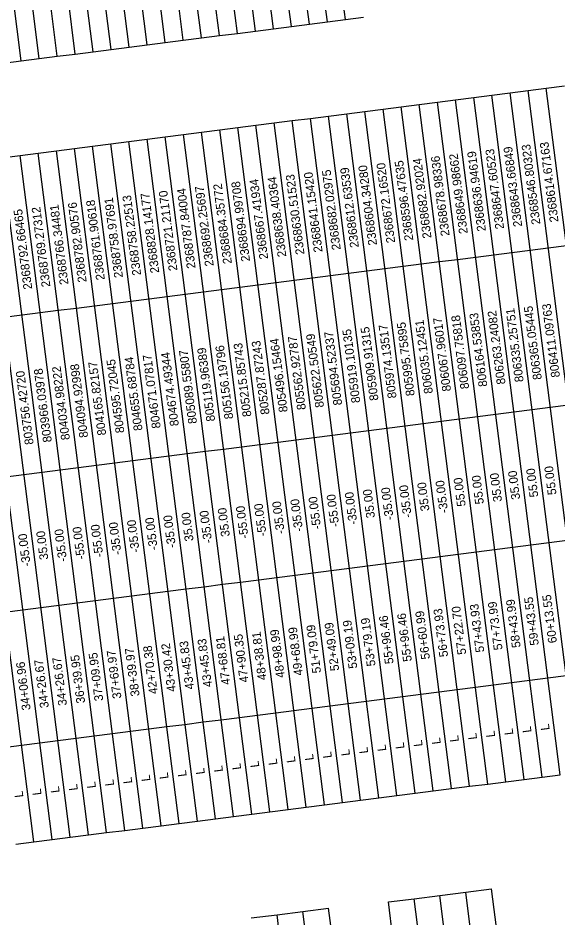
# Model space of a CAD drawing. Extents: x 2364621 to 2374814, y 792603 to 806745.
# Drawn here: x 2368280 to 2369750, y 798784 to 801237 of the extents above; entities that cross this region are included whole.
import ezdxf

# ---------------------------------------------------------------- set-up
doc = ezdxf.new("R2010")
doc.units = 0
doc.layers.add('CTL Sheet Table Cell', color=7, linetype='Continuous')
doc.layers.add('CTL Sheet Text', color=7, linetype='Continuous')

msp = doc.modelspace()

# ---------------------------------------------------------------- linework, layer by layer
at = {"layer": 'CTL Sheet Table Cell'}
for p, q in [((2369025.4, 801214.3), (2368791.2, 803048)), ((2369074.6, 801220.5), (2368840.4, 803054.3)), ((2369123.7, 801226.8), (2368889.5, 803060.6)), ((2369172.8, 801233.1), (2368938.6, 803066.8)), ((2368829, 801189.2), (2368594.8, 803022.9)), ((2368878.1, 801195.4), (2368643.9, 803029.2)), ((2368927.2, 801201.7), (2368693, 803035.5)), ((2368976.3, 801208), (2368742.1, 803041.7)), ((2368632.5, 801164.1), (2368398.3, 802997.8)), ((2368681.6, 801170.4), (2368447.4, 803004.1)), ((2368730.7, 801176.6), (2368496.5, 803010.4)), ((2368779.9, 801182.9), (2368545.7, 803016.6)), ((2368436, 801139), (2368201.8, 802972.7)), ((2368485.1, 801145.3), (2368250.9, 802979)), ((2368534.3, 801151.5), (2368300.1, 802985.3)), ((2368583.4, 801157.8), (2368349.2, 802991.5)), ((2368288.7, 801120.2), (2368054.5, 802953.9)), ((2368337.8, 801126.4), (2368103.6, 802960.2)), ((2368386.9, 801132.7), (2368152.7, 802966.5)), ((2369123.7, 801226.8), (2369172.8, 801233.1)), ((2369172.8, 801233.1), (2369221.9, 801239.4)), ((2368927.2, 801201.7), (2368976.3, 801208)), ((2368976.3, 801208), (2369025.4, 801214.3)), ((2369025.4, 801214.3), (2369074.6, 801220.5)), ((2369074.6, 801220.5), (2369123.7, 801226.8)), ((2368730.7, 801176.6), (2368779.9, 801182.9)), ((2368779.9, 801182.9), (2368829, 801189.2)), ((2368829, 801189.2), (2368878.1, 801195.4)), ((2368878.1, 801195.4), (2368927.2, 801201.7)), ((2368534.3, 801151.5), (2368583.4, 801157.8)), ((2368583.4, 801157.8), (2368632.5, 801164.1)), ((2368632.5, 801164.1), (2368681.6, 801170.4)), ((2368681.6, 801170.4), (2368730.7, 801176.6)), ((2368337.8, 801126.4), (2368386.9, 801132.7)), ((2368386.9, 801132.7), (2368436, 801139)), ((2368436, 801139), (2368485.1, 801145.3)), ((2368485.1, 801145.3), (2368534.3, 801151.5)), ((2368239.6, 801113.9), (2368288.7, 801120.2)), ((2368288.7, 801120.2), (2368337.8, 801126.4)), ((2369572.3, 801026.7), (2369621.8, 801033)), ((2369621.8, 801033), (2369671.3, 801039.3)), ((2369857.8, 799185.2), (2369621.8, 801033)), ((2369671.3, 801039.3), (2369720.8, 801045.7)), ((2369907.3, 799191.6), (2369671.3, 801039.3)), ((2369720.8, 801045.7), (2369770.3, 801052)), ((2369956.8, 799197.9), (2369720.8, 801045.7)), ((2369423.9, 801007.7), (2369473.4, 801014.1)), ((2369473.4, 801014.1), (2369522.8, 801020.4)), ((2369709.4, 799166.3), (2369473.4, 801014.1)), ((2369522.8, 801020.4), (2369572.3, 801026.7)), ((2369758.8, 799172.6), (2369522.8, 801020.4)), ((2369808.3, 799178.9), (2369572.3, 801026.7)), ((2369225.9, 800982.4), (2369275.4, 800988.8)), ((2369275.4, 800988.8), (2369324.9, 800995.1)), ((2369511.4, 799141), (2369275.4, 800988.8)), ((2369324.9, 800995.1), (2369374.4, 801001.4)), ((2369560.9, 799147.3), (2369324.9, 800995.1)), ((2369374.4, 801001.4), (2369423.9, 801007.7)), ((2369610.4, 799153.6), (2369374.4, 801001.4)), ((2369659.9, 799160), (2369423.9, 801007.7)), ((2369027.9, 800957.2), (2369077.4, 800963.5)), ((2369077.4, 800963.5), (2369126.9, 800969.8)), ((2369313.4, 799115.7), (2369077.4, 800963.5)), ((2369126.9, 800969.8), (2369176.4, 800976.1)), ((2369362.9, 799122), (2369126.9, 800969.8)), ((2369176.4, 800976.1), (2369225.9, 800982.4)), ((2369412.4, 799128.4), (2369176.4, 800976.1)), ((2369461.9, 799134.7), (2369225.9, 800982.4)), ((2368829.9, 800931.9), (2368879.4, 800938.2)), ((2368879.4, 800938.2), (2368928.9, 800944.5)), ((2369115.4, 799090.4), (2368879.4, 800938.2)), ((2368928.9, 800944.5), (2368978.4, 800950.8)), ((2369164.9, 799096.7), (2368928.9, 800944.5)), ((2368978.4, 800950.8), (2369027.9, 800957.2)), ((2369214.4, 799103.1), (2368978.4, 800950.8)), ((2369263.9, 799109.4), (2369027.9, 800957.2)), ((2368632, 800906.6), (2368681.5, 800912.9)), ((2368681.5, 800912.9), (2368730.9, 800919.2)), ((2368917.4, 799065.1), (2368681.5, 800912.9)), ((2368730.9, 800919.2), (2368780.4, 800925.6)), ((2368966.9, 799071.5), (2368730.9, 800919.2)), ((2368780.4, 800925.6), (2368829.9, 800931.9)), ((2369016.4, 799077.8), (2368780.4, 800925.6)), ((2369065.9, 799084.1), (2368829.9, 800931.9)), ((2368434, 800881.3), (2368483.5, 800887.6)), ((2368483.5, 800887.6), (2368533, 800894)), ((2368719.5, 799039.9), (2368483.5, 800887.6)), ((2368533, 800894), (2368582.5, 800900.3)), ((2368769, 799046.2), (2368533, 800894)), ((2368582.5, 800900.3), (2368632, 800906.6)), ((2368818.5, 799052.5), (2368582.5, 800900.3)), ((2368868, 799058.8), (2368632, 800906.6)), ((2368236, 800856), (2368285.5, 800862.3)), ((2368285.5, 800862.3), (2368335, 800868.7)), ((2368521.5, 799014.6), (2368285.5, 800862.3)), ((2368335, 800868.7), (2368384.5, 800875)), ((2368571, 799020.9), (2368335, 800868.7)), ((2368384.5, 800875), (2368434, 800881.3)), ((2368620.5, 799027.2), (2368384.5, 800875)), ((2368670, 799033.5), (2368434, 800881.3)), ((2368323.5, 798989.3), (2368087.5, 800837.1)), ((2368373, 798995.6), (2368137, 800843.4)), ((2368422.5, 799001.9), (2368186.5, 800849.7)), ((2368472, 799008.2), (2368236, 800856)), ((2369726.1, 800610.4), (2369775.6, 800616.7)), ((2369528.1, 800585.1), (2369577.6, 800591.4)), ((2369577.6, 800591.4), (2369627.1, 800597.8)), ((2369627.1, 800597.8), (2369676.6, 800604.1)), ((2369676.6, 800604.1), (2369726.1, 800610.4)), ((2369379.7, 800566.1), (2369429.2, 800572.5)), ((2369429.2, 800572.5), (2369478.6, 800578.8)), ((2369478.6, 800578.8), (2369528.1, 800585.1)), ((2369181.7, 800540.9), (2369231.2, 800547.2)), ((2369231.2, 800547.2), (2369280.7, 800553.5)), ((2369280.7, 800553.5), (2369330.2, 800559.8)), ((2369330.2, 800559.8), (2369379.7, 800566.1)), ((2368983.7, 800515.6), (2369033.2, 800521.9)), ((2369033.2, 800521.9), (2369082.7, 800528.2)), ((2369082.7, 800528.2), (2369132.2, 800534.5)), ((2369132.2, 800534.5), (2369181.7, 800540.9)), ((2368785.7, 800490.3), (2368835.2, 800496.6)), ((2368835.2, 800496.6), (2368884.7, 800502.9)), ((2368884.7, 800502.9), (2368934.2, 800509.3)), ((2368934.2, 800509.3), (2368983.7, 800515.6)), ((2368587.8, 800465), (2368637.2, 800471.3)), ((2368637.2, 800471.3), (2368686.7, 800477.6)), ((2368686.7, 800477.6), (2368736.2, 800484)), ((2368736.2, 800484), (2368785.7, 800490.3)), ((2368389.8, 800439.7), (2368439.3, 800446)), ((2368439.3, 800446), (2368488.8, 800452.4)), ((2368488.8, 800452.4), (2368538.3, 800458.7)), ((2368538.3, 800458.7), (2368587.8, 800465)), ((2368241.3, 800420.8), (2368290.8, 800427.1)), ((2368290.8, 800427.1), (2368340.3, 800433.4)), ((2368340.3, 800433.4), (2368389.8, 800439.7)), ((2369681.9, 800168.8), (2369731.4, 800175.1)), ((2369731.4, 800175.1), (2369780.9, 800181.4)), ((2369483.9, 800143.5), (2369533.4, 800149.8)), ((2369533.4, 800149.8), (2369582.9, 800156.2)), ((2369582.9, 800156.2), (2369632.4, 800162.5)), ((2369632.4, 800162.5), (2369681.9, 800168.8)), ((2369335.5, 800124.6), (2369384.9, 800130.9)), ((2369384.9, 800130.9), (2369434.4, 800137.2)), ((2369434.4, 800137.2), (2369483.9, 800143.5)), ((2369137.5, 800099.3), (2369187, 800105.6)), ((2369187, 800105.6), (2369236.5, 800111.9)), ((2369236.5, 800111.9), (2369286, 800118.2)), ((2369286, 800118.2), (2369335.5, 800124.6)), ((2368939.5, 800074), (2368989, 800080.3)), ((2368989, 800080.3), (2369038.5, 800086.6)), ((2369038.5, 800086.6), (2369088, 800092.9)), ((2369088, 800092.9), (2369137.5, 800099.3)), ((2368741.5, 800048.7), (2368791, 800055)), ((2368791, 800055), (2368840.5, 800061.3)), ((2368840.5, 800061.3), (2368890, 800067.7)), ((2368890, 800067.7), (2368939.5, 800074)), ((2368543.6, 800023.4), (2368593, 800029.7)), ((2368593, 800029.7), (2368642.5, 800036.1)), ((2368642.5, 800036.1), (2368692, 800042.4)), ((2368692, 800042.4), (2368741.5, 800048.7)), ((2368345.6, 799998.1), (2368395.1, 800004.4)), ((2368395.1, 800004.4), (2368444.6, 800010.8)), ((2368444.6, 800010.8), (2368494.1, 800017.1)), ((2368494.1, 800017.1), (2368543.6, 800023.4)), ((2368246.6, 799985.5), (2368296.1, 799991.8)), ((2368296.1, 799991.8), (2368345.6, 799998.1)), ((2369728.3, 799805.8), (2369777.8, 799812.2)), ((2369530.3, 799780.6), (2369579.8, 799786.9)), ((2369579.8, 799786.9), (2369629.3, 799793.2)), ((2369629.3, 799793.2), (2369678.8, 799799.5)), ((2369678.8, 799799.5), (2369728.3, 799805.8)), ((2369332.3, 799755.3), (2369381.8, 799761.6)), ((2369381.8, 799761.6), (2369431.3, 799767.9)), ((2369431.3, 799767.9), (2369480.8, 799774.2)), ((2369480.8, 799774.2), (2369530.3, 799780.6)), ((2369134.3, 799730), (2369183.8, 799736.3)), ((2369183.8, 799736.3), (2369233.3, 799742.6)), ((2369233.3, 799742.6), (2369282.8, 799749)), ((2369282.8, 799749), (2369332.3, 799755.3)), ((2368936.4, 799704.7), (2368985.9, 799711)), ((2368985.9, 799711), (2369035.4, 799717.3)), ((2369035.4, 799717.3), (2369084.8, 799723.7)), ((2369084.8, 799723.7), (2369134.3, 799730)), ((2368738.4, 799679.4), (2368787.9, 799685.7)), ((2368787.9, 799685.7), (2368837.4, 799692.1)), ((2368837.4, 799692.1), (2368886.9, 799698.4)), ((2368886.9, 799698.4), (2368936.4, 799704.7)), ((2368540.4, 799654.1), (2368589.9, 799660.5)), ((2368589.9, 799660.5), (2368639.4, 799666.8)), ((2368639.4, 799666.8), (2368688.9, 799673.1)), ((2368688.9, 799673.1), (2368738.4, 799679.4)), ((2368342.4, 799628.9), (2368391.9, 799635.2)), ((2368391.9, 799635.2), (2368441.4, 799641.5)), ((2368441.4, 799641.5), (2368490.9, 799647.8)), ((2368490.9, 799647.8), (2368540.4, 799654.1)), ((2368243.4, 799616.2), (2368292.9, 799622.5)), ((2368292.9, 799622.5), (2368342.4, 799628.9)), ((2369725.1, 799436.6), (2369774.6, 799442.9)), ((2369527.2, 799411.3), (2369576.6, 799417.6)), ((2369576.6, 799417.6), (2369626.1, 799423.9)), ((2369626.1, 799423.9), (2369675.6, 799430.2)), ((2369675.6, 799430.2), (2369725.1, 799436.6)), ((2369329.2, 799386), (2369378.7, 799392.3)), ((2369378.7, 799392.3), (2369428.2, 799398.6)), ((2369428.2, 799398.6), (2369477.7, 799405)), ((2369477.7, 799405), (2369527.2, 799411.3)), ((2369131.2, 799360.7), (2369180.7, 799367)), ((2369180.7, 799367), (2369230.2, 799373.4)), ((2369230.2, 799373.4), (2369279.7, 799379.7)), ((2369279.7, 799379.7), (2369329.2, 799386)), ((2368933.2, 799335.4), (2368982.7, 799341.8)), ((2368982.7, 799341.8), (2369032.2, 799348.1)), ((2369032.2, 799348.1), (2369081.7, 799354.4)), ((2369081.7, 799354.4), (2369131.2, 799360.7)), ((2368735.3, 799310.1), (2368784.7, 799316.5)), ((2368784.7, 799316.5), (2368834.2, 799322.8)), ((2368834.2, 799322.8), (2368883.7, 799329.1)), ((2368883.7, 799329.1), (2368933.2, 799335.4)), ((2368537.3, 799284.9), (2368586.8, 799291.2)), ((2368586.8, 799291.2), (2368636.3, 799297.5)), ((2368636.3, 799297.5), (2368685.8, 799303.8)), ((2368685.8, 799303.8), (2368735.3, 799310.1)), ((2368388.8, 799265.9), (2368438.3, 799272.2)), ((2368438.3, 799272.2), (2368487.8, 799278.5)), ((2368487.8, 799278.5), (2368537.3, 799284.9)), ((2368240.3, 799246.9), (2368289.8, 799253.3)), ((2368289.8, 799253.3), (2368339.3, 799259.6)), ((2368339.3, 799259.6), (2368388.8, 799265.9)), ((2369709.4, 799166.3), (2369758.8, 799172.6)), ((2369511.4, 799141), (2369560.9, 799147.3)), ((2369560.9, 799147.3), (2369610.4, 799153.6)), ((2369610.4, 799153.6), (2369659.9, 799160)), ((2369659.9, 799160), (2369709.4, 799166.3)), ((2369313.4, 799115.7), (2369362.9, 799122)), ((2369362.9, 799122), (2369412.4, 799128.4)), ((2369412.4, 799128.4), (2369461.9, 799134.7)), ((2369461.9, 799134.7), (2369511.4, 799141)), ((2369115.4, 799090.4), (2369164.9, 799096.7)), ((2369164.9, 799096.7), (2369214.4, 799103.1)), ((2369214.4, 799103.1), (2369263.9, 799109.4)), ((2369263.9, 799109.4), (2369313.4, 799115.7)), ((2368917.4, 799065.1), (2368966.9, 799071.5)), ((2368966.9, 799071.5), (2369016.4, 799077.8)), ((2369016.4, 799077.8), (2369065.9, 799084.1)), ((2369065.9, 799084.1), (2369115.4, 799090.4)), ((2368719.5, 799039.9), (2368769, 799046.2)), ((2368769, 799046.2), (2368818.5, 799052.5)), ((2368818.5, 799052.5), (2368868, 799058.8)), ((2368868, 799058.8), (2368917.4, 799065.1)), ((2368571, 799020.9), (2368620.5, 799027.2)), ((2368620.5, 799027.2), (2368670, 799033.5)), ((2368670, 799033.5), (2368719.5, 799039.9)), ((2368373, 798995.6), (2368422.5, 799001.9)), ((2368422.5, 799001.9), (2368472, 799008.2)), ((2368472, 799008.2), (2368521.5, 799014.6)), ((2368521.5, 799014.6), (2368571, 799020.9)), ((2368274, 798983), (2368323.5, 798989.3)), ((2368323.5, 798989.3), (2368373, 798995.6)), ((2369430.6, 798843.4), (2369500.9, 798852.4)), ((2369500.9, 798852.4), (2369571.2, 798861.4)), ((2369752.3, 796883.9), (2369500.9, 798852.4)), ((2369822.6, 796892.9), (2369571.2, 798861.4)), ((2369290, 798825.5), (2369360.3, 798834.4)), ((2369541.4, 796857), (2369290, 798825.5)), ((2369360.3, 798834.4), (2369430.6, 798843.4)), ((2369611.7, 796865.9), (2369360.3, 798834.4)), ((2369682, 796874.9), (2369430.6, 798843.4)), ((2369056.6, 798799.7), (2369126.9, 798808.7)), ((2369378.3, 796840.2), (2369126.9, 798808.7)), ((2368916, 798781.8), (2368986.3, 798790.8)), ((2368986.3, 798790.8), (2369056.6, 798799.7)), ((2369237.7, 796822.2), (2368986.3, 798790.8)), ((2369308, 796831.2), (2369056.6, 798799.7))]:
    msp.add_line(p, q, dxfattribs=at)

# ---------------------------------------------------------------- texts
at = {"layer": 'CTL Sheet Text'}
for s, height, p in [('2368643.66849', 23.76, (2369655.2, 800668.8)), ('2368546.80323', 23.76, (2369704.7, 800675.1)), ('2368614.67163', 23.76, (2369754.2, 800681.4)), ('2368649.98662', 23.76, (2369506.7, 800649.8)), ('2368636.94619', 23.76, (2369556.2, 800656.2)), ('2368647.60523', 23.76, (2369605.7, 800662.5)), ('2368672.16520', 23.76, (2369308.7, 800624.5)), ('2368596.47635', 23.76, (2369358.2, 800630.9)), ('2368682.92024', 23.76, (2369407.7, 800637.2)), ('2368678.98336', 23.76, (2369457.2, 800643.5)), ('2368641.15420', 23.76, (2369110.7, 800599.3)), ('2368682.02975', 23.76, (2369160.2, 800605.6)), ('2368612.63539', 23.76, (2369209.7, 800611.9)), ('2368604.34280', 23.76, (2369259.2, 800618.2)), ('2368694.99708', 23.76, (2368912.8, 800574)), ('2368667.41934', 23.76, (2368962.3, 800580.3)), ('2368638.40364', 23.76, (2369011.8, 800586.6)), ('2368630.51523', 23.76, (2369061.3, 800592.9)), ('2368721.21170', 23.76, (2368714.8, 800548.7)), ('2368787.84004', 23.76, (2368764.3, 800555)), ('2368692.25697', 23.76, (2368813.8, 800561.3)), ('2368684.35772', 23.76, (2368863.3, 800567.7)), ('2368761.90618', 23.76, (2368516.8, 800523.4)), ('2368758.97691', 23.76, (2368566.3, 800529.7)), ('2368758.22513', 23.76, (2368615.8, 800536.1)), ('2368828.14177', 23.76, (2368665.3, 800542.4)), ('2368792.66465', 23.76, (2368318.8, 800498.1)), ('2368769.27312', 23.76, (2368368.3, 800504.4)), ('2368766.34481', 23.76, (2368417.8, 800510.8)), ('2368782.90576', 23.76, (2368467.3, 800517.1)), ('806335.25751', 23.76, (2369659, 800245.2)), ('806365.05445', 23.76, (2369708.5, 800251.5)), ('806411.09763', 23.76, (2369758, 800257.9)), ('806097.75818', 23.76, (2369510.5, 800226.3)), ('806164.53853', 23.76, (2369560, 800232.6)), ('806263.24082', 23.76, (2369609.5, 800238.9)), ('805974.13517', 23.76, (2369312.5, 800201)), ('805995.75895', 23.76, (2369362, 800207.3)), ('806035.12451', 23.76, (2369411.5, 800213.6)), ('806067.96017', 23.76, (2369461, 800219.9)), ('805622.50549', 23.76, (2369114.5, 800175.7)), ('805694.52337', 23.76, (2369164, 800182)), ('805919.10135', 23.76, (2369213.5, 800188.3)), ('805909.91315', 23.76, (2369263, 800194.7)), ('805215.85743', 23.76, (2368916.6, 800150.4)), ('805287.87243', 23.76, (2368966.1, 800156.7)), ('805496.15464', 23.76, (2369015.6, 800163)), ('805562.92787', 23.76, (2369065.1, 800169.4)), ('804674.49344', 23.76, (2368718.6, 800125.1)), ('805089.55807', 23.76, (2368768.1, 800131.4)), ('805119.96389', 23.76, (2368817.6, 800137.8)), ('805156.19796', 23.76, (2368867.1, 800144.1)), ('804165.82157', 23.76, (2368520.6, 800099.8)), ('804595.72045', 23.76, (2368570.1, 800106.2)), ('804655.68784', 23.76, (2368619.6, 800112.5)), ('804671.07817', 23.76, (2368669.1, 800118.8)), ('803756.42720', 23.76, (2368322.6, 800074.5)), ('803966.03978', 23.76, (2368372.1, 800080.9)), ('804034.98222', 23.76, (2368421.6, 800087.2)), ('804094.92998', 23.76, (2368471.1, 800093.5)), ('55.00', 23.76, (2369699.1, 799931.1)), ('55.00', 23.76, (2369748.6, 799937.4)), ('55.00', 23.76, (2369501.1, 799905.8)), ('55.00', 23.76, (2369550.6, 799912.1)), ('35.00', 23.76, (2369600.1, 799918.5)), ('35.00', 23.76, (2369649.6, 799924.8)), ('-35.00', 23.76, (2369304.6, 799868.8)), ('-35.00', 23.76, (2369354.1, 799875.2)), ('35.00', 23.76, (2369402.1, 799893.2)), ('-35.00', 23.76, (2369453.1, 799887.8)), ('-55.00', 23.76, (2369106.7, 799843.6)), ('-55.00', 23.76, (2369156.2, 799849.9)), ('-35.00', 23.76, (2369205.6, 799856.2)), ('35.00', 23.76, (2369253.7, 799874.2)), ('-55.00', 23.76, (2368908.7, 799818.3)), ('-55.00', 23.76, (2368958.2, 799824.6)), ('-35.00', 23.76, (2369007.7, 799830.9)), ('-35.00', 23.76, (2369057.2, 799837.2)), ('-35.00', 23.76, (2368710.7, 799793)), ('35.00', 23.76, (2368758.7, 799811)), ('-35.00', 23.76, (2368809.7, 799805.6)), ('35.00', 23.76, (2368857.7, 799823.6)), ('-55.00', 23.76, (2368512.7, 799767.7)), ('-35.00', 23.76, (2368562.2, 799774)), ('-35.00', 23.76, (2368611.7, 799780.3)), ('-35.00', 23.76, (2368661.2, 799786.7)), ('35.00', 23.76, (2368362.8, 799760.4)), ('-35.00', 23.76, (2368413.7, 799755.1)), ('-55.00', 23.76, (2368463.2, 799761.4)), ('-35.00', 23.76, (2368314.8, 799742.4)), ('60+13.55', 23.76, (2369749.9, 799533.1)), ('57+43.93', 23.76, (2369552, 799507.8)), ('57+73.99', 23.76, (2369601.5, 799514.1)), ('58+43.99', 23.76, (2369650.9, 799520.4)), ('59+43.55', 23.76, (2369700.4, 799526.8)), ('55+96.46', 23.76, (2369354, 799482.5)), ('56+60.99', 23.76, (2369403.5, 799488.8)), ('56+73.93', 23.76, (2369453, 799495.2)), ('57+22.70', 23.76, (2369502.5, 799501.5)), ('52+49.09', 23.76, (2369156, 799457.2)), ('53+09.19', 23.76, (2369205.5, 799463.5)), ('53+79.19', 23.76, (2369255, 799469.9)), ('55+96.46', 23.76, (2369304.5, 799476.2)), ('48+38.81', 23.76, (2368958, 799431.9)), ('48+98.99', 23.76, (2369007.5, 799438.3)), ('49+68.99', 23.76, (2369057, 799444.6)), ('51+79.09', 23.76, (2369106.5, 799450.9)), ('43+45.83', 23.76, (2368760.1, 799406.7)), ('43+45.83', 23.76, (2368809.5, 799413)), ('47+68.81', 23.76, (2368859, 799419.3)), ('47+90.35', 23.76, (2368908.5, 799425.6)), ('38+39.97', 23.76, (2368611.6, 799387.7)), ('42+70.38', 23.76, (2368661.1, 799394)), ('43+30.42', 23.76, (2368710.6, 799400.3)), ('34+26.67', 23.76, (2368413.6, 799362.4)), ('36+39.95', 23.76, (2368463.1, 799368.7)), ('37+09.95', 23.76, (2368512.6, 799375)), ('37+69.97', 23.76, (2368562.1, 799381.4)), ('34+06.96', 23.76, (2368314.6, 799349.8)), ('34+26.67', 23.76, (2368364.1, 799356.1)), ('L', 23.8, (2369581.5, 799276.2)), ('L', 23.8, (2369631, 799282.5)), ('L', 23.8, (2369680.5, 799288.8)), ('L', 23.8, (2369730, 799295.1)), ('L', 23.8, (2369383.6, 799250.9)), ('L', 23.8, (2369433.1, 799257.2)), ('L', 23.8, (2369482.6, 799263.5)), ('L', 23.8, (2369532, 799269.9)), ('L', 23.8, (2369185.6, 799225.6)), ('L', 23.8, (2369235.1, 799231.9)), ('L', 23.8, (2369284.6, 799238.2)), ('L', 23.8, (2369334.1, 799244.6)), ('L', 23.8, (2369037.1, 799206.6)), ('L', 23.8, (2369086.6, 799213)), ('L', 23.8, (2369136.1, 799219.3)), ('L', 23.8, (2368839.1, 799181.4)), ('L', 23.8, (2368888.6, 799187.7)), ('L', 23.8, (2368938.1, 799194)), ('L', 23.8, (2368987.6, 799200.3)), ('L', 23.8, (2368641.2, 799156.1)), ('L', 23.8, (2368690.6, 799162.4)), ('L', 23.8, (2368740.1, 799168.7)), ('L', 23.8, (2368789.6, 799175)), ('L', 23.8, (2368443.2, 799130.8)), ('L', 23.8, (2368492.7, 799137.1)), ('L', 23.8, (2368542.2, 799143.4)), ('L', 23.8, (2368591.7, 799149.7)), ('L', 23.8, (2368294.7, 799111.8)), ('L', 23.8, (2368344.2, 799118.1)), ('L', 23.8, (2368393.7, 799124.5))]:
    msp.add_text(s, height=height, rotation=97.2784, dxfattribs=at).set_placement(p)

doc.saveas('drawing.dxf')
